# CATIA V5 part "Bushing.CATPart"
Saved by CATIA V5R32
Part number: Bushing
Bounding box of the stored display mesh (mm): x -13.45 to 13.45, y 0 to 63, z -13.45 to 13.45
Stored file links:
  D:\PROJECTS\Project 2022\CATIA V5 6R 2022\Resources\Part Files\c12_catia_v5_6r2022_prt\c12_catia_v5-6r2022 figr_12-49\Bushing.CATPart
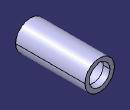
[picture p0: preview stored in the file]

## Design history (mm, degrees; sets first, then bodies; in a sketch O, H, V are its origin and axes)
Body1 (main body)
  Sketch1 on zx-plane, origin (0, 0, 0), H (-1, 0, 0), V (0, 0, 1)
    circle A1 centre (0, 0) radius 9.5
    circle A2 centre (0, 0) radius 13.45
    radius A1 = 9.5
    radius A2 = 13.45
  Pad1: profile Sketch1, direction (0, 1, 0), length 63
  Sketch2 on face of Pad1, origin (0, 63, 0), H (-1, 0, 0), V (0, 0, 1)
    line L1 (-1.5, 9.3808) -> (1.5, 9.3808)
    line L2 (1.5, 9.3808) -> (1.5, 10.1808)
    line L3 (1.5, 10.1808) -> (-1.5, 10.1808)
    line L4 (-1.5, 10.1808) -> (-1.5, 9.3808)
    point P2 (1.5, 9.3808)
    reference projected circle E1 centre (0, 0) radius 9.5 from edge of Pad1
    length L3 = 3
    length L2 = 0.8
    distance V L4 = 1.5
    horizontal: L1 H, L3 H
    vertical: L2 V, L4 V
    coincidence: P2 E1
  Pocket1: profile Sketch2, direction (0, -1, 0), through (limit type 6)
  Sketch3 on xy-plane, origin (0, 0, 0), H (1, 0, 0), V (0, 1, 0)
    line L1 (9.5, 57) -> (10.3, 57)
    line L2 (10.3, 57) -> (10.3, 49)
    line L3 (10.3, 49) -> (9.5, 49)
    line L4 (9.5, 49) -> (9.5, 57)
    reference projected line E1 (13.45, 63) -> (-13.45, 63) from edge of Pad1
    length L2 = 8
    length L1 = 0.8
    distance L3 E1 = 14
    distance V L4 = 9.5
    horizontal: L1 H, L3 H
    vertical: L2 V, L4 V
  Groove1: profile Sketch3, axis axis of face of Pad1, angle 360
